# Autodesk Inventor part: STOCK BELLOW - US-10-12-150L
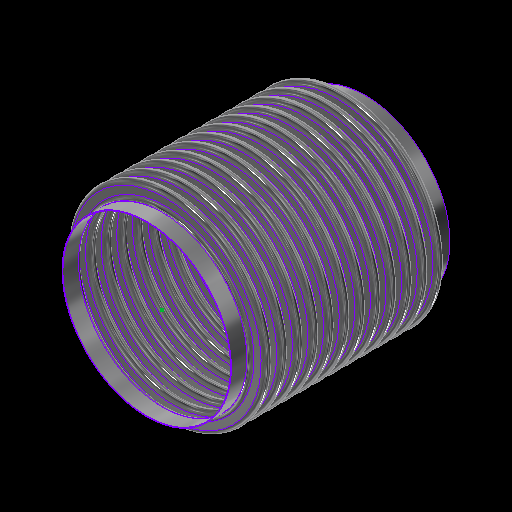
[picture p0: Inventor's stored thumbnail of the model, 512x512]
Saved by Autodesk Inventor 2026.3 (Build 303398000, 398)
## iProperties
Category: 18 GA (0.048 THICK)
RuleStatus: InUse
Created: 2024-01
Part Number: STOCK BELLOW - US-10-12-150L
Project: =STOCK BELLOWS: <Stock Number><SFILL>
Material: ASTM A240-304
Description: =STOCK BELLOWS: <Stock Number>, <SID_> I.D., <SOD_> O.D., <SPLY_> PLY, <Category>, <SNET_CONS> CONS.<PITCH_><STANGENT_> TANGENT<SFILL>
Document SubType Name: Sheet Metal
Designer: GS
Stock Number: U.S-10-12-150L
Surface Area: 15083.6 cm^2
Volume: 915.651 cm^3
Sheet Metal Rule: Default
Appearance: STAINLESS STEEL
Mass: 7377.66 g
Density: 8.05729 g/cm^3
THK: 0.036
ID: 3.500
OD: 4.250
CONS_: 2
PITCH: 0.500
TANGENT: 0.500
BELLOWS_UPSET: 0.000
d79: 1.000
d82: 1.000
d83: 26.000
d84: 24.000
d174: 8
d214: 8
STHK_: 0.048
SID_: 10.750
SOD_: 12.750
SPITCH_: 1.000
STANGENT__: 1.000
SBELLOWS_UPSET_: 0.000
SDIFF_TAN: 1.000
d252: 2
d275: 2
d287: 0.050
d289: 0.500
d290: 0.000
SOD_NECK: 10 7/8
PLY: 1
PSET: 4.178
PBAR: 1.035
COUNTER: 1.500
NET_TUBE: 3.071
CONS: 2
S_CONS: 0
NET_CONS: 2
ID_M: 88.90 mm
OD_M: 107.95 mm
THK_M: 0.91 mm
ID_U: 3.500 in
OD_U: 4.250 in
THK_U: 0.036 in
TANGENT2: 0.500
TAN_TO_TAN: 1.000 in
d80: 2.571
d81: 10
SID: 2.375
SCONS_: 12
SPITCH: 0.250
STANGENT_: 1.000
SBELLOWS_UPSET: 0.000
SNET_CONS: 12
SS_CONS: 0
SCONS: 8
d190: 8
d191: 1
d192: 1
d193: 8
d194: 0
SIZE: 10.00
PRESSURE: 150
d230: 8
STANGENT: 4.000
SPLY_: 1
d233: 8
d234: 0
d263: 2
d265: 1
d268: 2
d269: 0
d286: 2
d288: 1
d291: 2
d292: 0
SREROLL: 0.750
BLETP: 1.000 ul
PRES_Copy: 85
MATTABLE: 20 GA (0.036 THICK)
PART_NUMBER: U.S-10-12-150L
PITCH_: =, <SPITCH_> PITCH,
CFILL: .
SFILL: .
MESH: ,
COMP: 2.22
EXT: 1.11
LAT: 0.75
ANG: 573
ASR: 1990
LSR: 2575
ANSR: 539
PRES: 150
COMPM: 22.2
EXTM: 11.1
LATM: 7.50
ASRM: 348.509
PRESM: 10.342
LSRM: 450.960
ANSRM: 94.395
TEMPMIN: 20
TEMPMAX: 800
TEMPMINM: -7
TEMPMAXM: 427
WEIGHTM: 7.378
WEIGHT: 16.265
Author: GS
Keywords: 20 GA (0.036 THICK)
Comments: =STOCK BELLOW - <STOCK NUMBER>
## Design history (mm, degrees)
sketch "Sketch2"
  geometry: L1 (0, -177.245)-(0, 562.856) reference; L2 (45.364, 0)-(44.45, 0); L3 (48.082, -2.718)-(50.343, -2.718); L4 (48.082, -3.632)-(50.343, -3.632); L5 (50.343, -9.982)-(48.082, -9.982); L6 (50.343, -9.068)-(48.082, -9.068); L7 (45.364, -12.7)-(44.45, -12.7); L8 (48.082, 0)-(48.082, -12.7); L9 (50.343, -6.35)-(53.975, -6.35); L10 (44.45, 0)-(44.45, -12.7); L11 (20.376, 102.841)-(20.376, 101.926); L12 (58.262, 457.127)-(58.262, 349.177); L13 (58.262, 444.427)-(58.262, 336.477); L14 (93.133, -58.817)-(93.133, -71.517); L15 (118.746, -66.401)-(118.746, -66.401); L16 (50.343, -9.068)-(50.343, -9.982); L17 (48.082, -9.068)-(48.082, -9.982); L18 (48.082, -9.525)-(50.343, -9.525); L19 (53.975, 0)-(53.975, -12.7); L20 (-50.343, -9.068)-(-50.343, -9.982); L21 (-50.343, -2.718)-(-48.082, -2.718); L22 (-50.343, -3.632)-(-48.082, -3.632); L23 (-48.082, -9.068)-(-50.343, -9.068); L24 (-50.343, -9.525)-(-48.082, -9.525); L25 (-48.082, -9.982)-(-50.343, -9.982); L26 (-48.082, -9.068)-(-48.082, -9.982); L27 (-44.45, 0.653)-(-44.45, -12.047); L28 (-48.082, -6.35)-(-44.45, -6.35); L29 (-50.343, 0.653)-(-50.343, -12.7); L30 (-53.061, 0)-(-53.975, 0); L31 (-53.975, 0)-(-53.975, -12.7); L32 (-53.061, -12.7)-(-53.975, -12.7); A1 r 2.718 centre (48.082, 0) between (45.364, 0) and (48.082, -2.718); A2 r 3.632 centre (48.082, 0) between (44.45, 0) and (48.082, -3.632); A3 r 3.632 centre (50.343, -6.35) between (50.343, -9.982) and (50.343, -2.718); A4 r 2.718 centre (50.343, -6.35) between (50.343, -9.068) and (50.343, -3.632); A5 r 2.718 centre (48.082, -12.7) between (48.082, -9.982) and (45.364, -12.7); A6 r 3.632 centre (48.082, -12.7) between (48.082, -9.068) and (44.45, -12.7); A7 r 3.175 centre (50.343, -6.35) between (50.343, -9.525) and (53.518, -6.35); A8 r 3.175 centre (48.082, -12.7) between (48.082, -9.525) and (44.907, -12.7); A9 r 2.718 centre (-50.343, -12.7) between (-50.343, -9.982) and (-53.061, -12.7); A10 r 2.718 centre (-48.082, -6.35) between (-48.082, -9.068) and (-48.082, -3.632); A11 r 3.175 centre (-48.082, -6.35) between (-48.082, -9.525) and (-44.907, -6.35); A12 r 3.632 centre (-48.082, -6.35) between (-48.082, -9.982) and (-48.082, -2.718); A13 r 3.175 centre (-50.343, -12.7) between (-50.343, -9.525) and (-53.518, -12.7); A14 r 3.632 centre (-50.343, -12.7) between (-50.343, -9.068) and (-53.975, -12.7); A15 r 2.718 centre (-50.343, 0) between (-53.061, 0) and (-50.343, -2.718); A16 r 3.632 centre (-50.343, 0) between (-53.975, 0) and (-50.343, -3.632); 10 further points
  constraints: 62 end point, 38 point on circle, 20 tangent, 16 centre point, 12 parallel, 9 midpoint, 7 vertical, 6 coincident, 6 concentric, 6 point on line, 4 equal radius, 4 perpendicular, 3 horizontal, 1 collinear, 1 horizontal alignment, 10 other
  dimensions: "THK" = 0.9144 distance of L11.start L11.end; "ID" = 88.9 distance of L11.end point (20.376, 13.026); "OD" = 107.95 distance of L12.start L12.end; "PITCH" = 12.7 distance of L12.start L13.start; "TANGENT" = 12.7 distance of L14.start L14.end; "BELLOWS_UPSET" = 0 distance of L15.start L15.end; "d43" = 88.9 diameter of L10 L1 (= ID); "d44" = 107.95 diameter of L9.end L1 (= OD); "d45" = 0.9144 distance between parallel lines of L5 L6 (computed from THK, PLY); "d46" = 3.6322 radius of A3 (computed from PITCH, THK, PLY); "UPSET_PITCH" = 12.7 distance of L2.end L7.end (derived); "SIDEWALL_ANGLE" = 360 deg dimension on L3 L9 (derived); "CON_GAP" = 5.4356 distance of point (48.082, -9.068) point (48.082, -3.632) (derived); "TAN1" = 4.98728 dimension on A8 (derived); "TAN2" = 4.98728 dimension on A7 (derived); "LEG1" = 2.2606 distance of L18.start L18.end (derived); "d278" = 0.9144 distance between parallel lines of L25 L23 (derived); "d279" = 3.6322 radius of A12 (derived); "d280" = 12.7 distance of L30.end L31.end (derived); "d281" = 360 deg dimension on L21 L28 (derived); "d282" = 5.4356 distance of point (-50.343, -9.068) point (-50.343, -3.632) (derived); "d283" = 4.98728 dimension on A13 (derived); "d284" = 4.98728 dimension on A11 (derived); "d285" = 2.2606 distance of L24.start L24.end (derived); "d293" = 88.9 diameter of L27 L1 (derived); "d294" = 107.95 diameter of L31 L1 (derived)
  node "Sketch Rectangular Pattern1" dims "d31" = 25.4, "ID" = 88.9
  node "Sketch Rectangular Pattern2" dims "d39" = 25.4, "PITCH" = 12.7
revolve "CONS" stored, may be unused: angle "d48" = 90 deg
node "BELLOW MIDPLANE"
pattern_linear "Rectangular Pattern2" dims "d52" = 12.7 (= UPSET_PITCH)
sketch "Sketch5"
  geometry: C1 r 45.364 at (0, 0) reference; C2 r 44.45 at (0, 0) reference
extrude "TANGENT" new body sketch "Sketch5" distance "d53" = 12.7 (= TANGENT); taper "d54" = 0 deg
revolve "SAMETAN" stored, may be unused: angle "d65" = 90 deg
revolve "DIFFTAN" stored, may be unused: angle "d70" = 90 deg
sketch "Sketch9"
  geometry: L1 (53.319, 0)-(-53.319, 0) reference; L2 (0, -17.78)-(0, 17.78) reference; L3 (38.085, 0)-(-38.085, 0); L4 (38.085, -11.906)-(38.085, 11.906); L5 (25.385, -11.906)-(25.385, 11.906); L6 (13.15, 11.906)-(13.15, -11.906); L7 (-25.385, -11.906)-(-25.385, 11.906); L8 (-38.085, -11.906)-(-38.085, 11.906); L9 (37.291, -11.906)-(37.291, 11.906); L10 (38.085, -11.906)-(37.291, -11.906); L11 (38.085, 11.906)-(37.291, 11.906); L12 (13.546, 11.906)-(12.753, 11.906); L13 (12.753, 11.906)-(12.753, -11.906); L14 (12.753, -11.906)-(13.546, -11.906); L15 (13.546, -11.906)-(13.546, 11.906); L16 (-13.546, 11.906)-(-13.546, -11.906); L17 (-13.15, 11.906)-(-13.15, -11.906); L18 (-13.546, -11.906)-(-12.753, -11.906); L19 (-12.753, -11.906)-(-12.753, 11.906); L20 (-12.753, 11.906)-(-13.546, 11.906); L21 (-38.085, -11.906)-(-37.291, -11.906); L22 (-37.291, -11.906)-(-37.291, 11.906); L23 (-37.291, 11.906)-(-38.085, 11.906); L24 (-38.085, 11.906)-(-38.085, -11.906); L25 (38.085, -0.397)-(-38.085, -0.397); L26 (-38.085, -0.397)-(-38.085, 0.397); L27 (-38.085, 0.397)-(38.085, 0.397); L28 (38.085, 0.397)-(38.085, -0.397); L29 (-38.085, 11.906)-(38.085, 11.906); L30 (38.085, 11.906)-(38.085, 12.7); L31 (38.085, 12.7)-(-38.085, 12.7); L32 (-38.085, 12.7)-(-38.085, 11.906); L33 (38.085, -11.906)-(-38.085, -11.906); L34 (-38.085, -11.906)-(-38.085, -12.7); L35 (-38.085, -12.7)-(38.085, -12.7); L36 (38.085, -12.7)-(38.085, -11.906); 30 further points
  constraints: 68 end point, 13 midpoint, 13 parallel, 8 horizontal, 7 perpendicular, 6 equal length, 3 point on line, 2 vertical, 14 other
  dimensions: "d115" = 23.8125 distance of L4.start L4.end (derived); "d116" = 12.7 distance between parallel lines of L4 L5 (derived); "d117" = 12.23516 distance between parallel lines of L5 L6 (derived); "d125" = 38.53427 distance between parallel lines of L7 L6 (derived); "d127" = 12.7 distance between parallel lines of L8 L7 (derived); "d128" = 24.93516 distance between parallel lines of L6 L4 (derived); "d130" = 76.16943 distance between parallel lines of L8 L4 (derived); "RULER_THK" = 0.79375 distance between parallel lines of L4 L9; "d135" = 0.79375 distance of L13.end L14.end (derived); "d138" = 26.29911 distance of L13.end L16.end (derived); "d143" = 0.79375 distance of L22.end L8.end (derived); "d144" = 0.79375 distance between parallel lines of L27 L25 (derived)
extrude "RULER" join sketch "Sketch9" distance "d149" = 0.79375 (derived); taper "d150" = 0 deg
extrude "BARS" join sketch "Sketch9" distance "d151" = 0.79375 (derived); taper "d152" = 0 deg
pattern_linear "Rectangular Pattern4" dims "d155" = 26.29911 (derived)
sketch "Sketch13"
  geometry: L1 (93.149, -52.467)-(93.149, -77.867); L2 (137.744, 0)-(136.525, 0); L3 (137.744, -25.4)-(136.525, -25.4); L4 (154.965, -19.66)-(143.485, -19.66); L5 (154.965, -18.44)-(143.485, -18.44); L6 (154.965, -12.7)-(161.925, -12.7); L7 (143.485, -5.74)-(154.965, -5.74); L8 (143.485, 0)-(143.485, -25.4); L9 (136.525, 0)-(136.525, -25.4); L10 (58.254, -172.581)-(58.254, -496.431); L11 (58.254, -197.981)-(58.254, -521.831); L12 (58.254, -248.781)-(58.254, -572.631); L13 (58.254, -274.181)-(58.254, -598.031); L14 (58.254, -299.581)-(58.254, -623.431); L15 (58.254, -324.981)-(58.254, -648.831); L16 (58.254, -350.381)-(58.254, -674.231); L17 (58.254, -223.381)-(58.254, -547.231); L18 (20.376, 103.145)-(20.376, 101.926); L19 (143.485, -6.96)-(154.965, -6.96); L20 (0, -829.706)-(0, 258.621) reference; L21 (-32.385, 0)-(194.31, 0) reference; A1 r 5.74 centre (143.485, 0) between (137.744, 0) and (143.485, -5.74); A2 r 5.74 centre (143.485, -25.4) between (143.485, -19.66) and (137.744, -25.4); A3 r 6.96 centre (143.485, -25.4) between (143.485, -18.44) and (136.525, -25.4); A4 r 5.74 centre (154.965, -12.7) between (154.965, -18.44) and (154.965, -6.96); A5 r 6.96 centre (154.965, -12.7) between (154.965, -19.66) and (154.965, -5.74); A6 r 6.96 centre (143.485, 0) between (136.525, 0) and (143.485, -6.96); 6 further points; 1 other entity
  constraints: 38 end point, 15 point on circle, 9 tangent, 6 centre point, 6 parallel, 5 vertical alignment, 4 point on line, 4 vertical, 3 coincident, 3 concentric, 2 collinear, 2 equal radius, 1 horizontal, 1 perpendicular, 23 other
  dimensions: "SBELLOWS_UPSET_" = 0 distance of point (118.762, -66.401) point (118.762, -66.401); "STOTAL_THK_BELLOW__" = 1.2192 distance between parallel lines of L4 L5 (derived); "d224" = 6.9596 radius of A5 (derived); "d225" = 25.4 distance of L2.end L3.end (derived); "SSIDEWALL_ANGLE_" = 360 deg dimension on L7 L6 (derived); "SSCON_GAP_" = 11.4808 distance of point (143.485, -18.44) point (143.485, -6.96) (derived); "d235" = 273.05 diameter of L9 L20 (derived); "d236" = 323.85 diameter of L6.end L20 (derived)
  node "Sketch Rectangular Pattern4" dims "d228" = 25.4
  node "Sketch Rectangular Pattern5" dims "d229" = 25.4
revolve "SBELLOW" stored, may be unused: angle "d197" = 90 deg
pattern_linear "Rectangular Pattern5" dims "d204" = 25.4 (derived)
revolve "STANGENT" stored, may be unused: angle "d240" = 90 deg
revolve "SSAMETAN" stored, may be unused: angle "d241" = 90 deg
revolve "SDIFFTAN" stored, may be unused: angle "d246" = 90 deg
revolve "INVCON" stored, may be unused: angle "d295" = 90 deg
pattern_linear "Rectangular Pattern6" dims "d298" = 12.7 (derived)
revolve "INVTANGENT" stored, may be unused: angle "d302" = 90 deg
revolve "INVSAMETAN" stored, may be unused: angle "d307" = 90 deg
revolve "INVDIFFTAN" stored, may be unused: angle "d312" = 90 deg
sketch "ID BELLOW MOUNT CALC"
  geometry: L1 (44.45, 0)-(38.1, 0); L2 (38.1, 0)-(38.1, 12.7); L3 (38.1, 12.7)-(44.45, 12.7); L4 (44.45, 12.7)-(44.45, 0); L5 (36.513, 12.7)-(35.598, 12.7); L6 (35.598, 12.7)-(35.598, 0); L7 (35.598, 0)-(36.513, 0); L8 (36.513, 0)-(36.513, 12.7); L9 (0, -2.54)-(0, 15.24) reference; L10 (-8.89, 0)-(53.34, 0) reference; 1 further point
  constraints: 16 end point, 5 parallel, 2 collinear, 2 horizontal, 2 perpendicular
  dimensions: "d314" = 12.7 distance of L5.end L6.end (derived); "d315" = 0.9144 distance of L5.start L5.end (derived); "IG" = 1.5875 distance between parallel lines of L2 L8; "PIPE_OD" = 88.9 diameter of L4 L9; "PIPE_WALL" = 6.35 distance of L2.end L3.end; "ID_MT_BELLOW" = 71.1962 diameter of L6 L9 (derived)
revolve "CFILL" stored, may be unused: angle "d320" = 90 deg
pattern_linear "Rectangular Pattern7" dims "d323" = 12.7 (derived)
revolve "SFILL" stored, may be unused: angle "d324" = 90 deg
pattern_linear "Rectangular Pattern8" dims "d327" = 25.4 (derived)
node "STOCK BELLOW MIDPLANE"
node "BELLOW"
sketch "Sketch6"
  geometry: L1 (-12.7, 45.364)-(0, 45.364); L2 (0, 45.364)-(0, 44.45); L3 (0, 44.45)-(-12.7, 44.45); L4 (-12.7, 44.45)-(-12.7, 45.364); L5 (10.16, 0)-(-60.96, 0) reference; L6 (-38.1, -89.422)-(-38.1, 153.44) reference; 1 further point
  constraints: 8 end point, 2 parallel, 1 horizontal, 1 perpendicular
  dimensions: "d61" = 12.7 distance of L2.end L3.end (derived); "d62" = 0.9144 distance of L1.end L2.end (derived); "d63" = 88.9 diameter of L3 L5 (derived); "d64" = 25.4 distance between parallel lines of L4 L6 (derived)
sketch "Sketch12"
  geometry: 1 further point
sketch "Sketch14"
  geometry: L1 (-25.4, 137.744)-(0, 137.744); L2 (0, 137.744)-(0, 136.525); L3 (0, 136.525)-(-25.4, 136.525); L4 (-25.4, 136.525)-(-25.4, 137.744); L5 (5.08, 0)-(-30.48, 0) reference; L6 (0, -27.549)-(0, 165.293) reference; 1 further point
  constraints: 8 end point, 2 parallel, 1 collinear, 1 horizontal, 1 perpendicular
  dimensions: "d237" = 1.2192 distance of L3.end L1.start (derived); "d238" = 273.05 diameter of L3 L5 (derived); "d239" = 25.4 distance of L1.start L1.end (derived); "SOD_NECK" = 275.4884 diameter of L1 L5 (derived)
sketch "Sketch15"
  geometry: L1 (-27.549, 0)-(165.293, 0) reference; L2 (136.525, -304.8)-(137.744, -304.8); L3 (137.744, -304.8)-(137.744, -330.2); L4 (137.744, -330.2)-(136.525, -330.2); L5 (136.525, -330.2)-(136.525, -304.8); L6 (0, -398.78)-(0, 81.28) reference; 1 further point
  constraints: 8 end point, 2 parallel, 1 horizontal, 1 perpendicular
  dimensions: "d205" = 25.4 distance of L4.end L2.start (derived); "d206" = 1.2192 distance of L3.end L4.end (derived); "d207" = 273.05 diameter of L5 L6 (derived); "d208" = 304.8 distance between parallel lines of L1 L2 (derived)
node "TANGENT_"
node "SAME_TAN"
sketch "Sketch8"
  geometry: L1 (45.364, -25.4)-(44.45, -25.4); L2 (44.45, -25.4)-(44.45, -38.1); L3 (44.45, -38.1)-(45.364, -38.1); L4 (45.364, -38.1)-(45.364, -25.4); L5 (0, -48.26)-(0, 22.86) reference; L6 (-89.422, 0)-(153.44, 0) reference; 1 further point
  constraints: 8 end point, 2 parallel, 1 horizontal, 1 perpendicular
  dimensions: "d66" = 88.9 diameter of L2 L5 (derived); "TOTAL_THK_BELLOW" = 0.9144 distance of L2.end L3.end (derived); "d68" = 25.4 distance between parallel lines of L1 L6 (derived); "d69" = 12.7 distance of L1.end L2.end (derived)
node "DIFF_TAN"
node "Sketch Rectangular Pattern3" dims "d138" = 26.29911 (derived), "d141" = 25.4
node "SBELLOW_"
node "STANGENT_"
node "SSAME_TAN"
sketch "Sketch16"
  geometry: L1 (137.744, -304.8)-(136.525, -304.8); L2 (136.525, -304.8)-(136.525, -330.2); L3 (136.525, -330.2)-(137.744, -330.2); L4 (137.744, -330.2)-(137.744, -304.8); L5 (0, -398.78)-(0, 81.28) reference; L6 (-27.549, 0)-(165.293, 0) reference; 1 further point
  constraints: 8 end point, 2 parallel, 1 horizontal, 1 perpendicular
  dimensions: "SDIFF_TAN" = 25.4 distance of L3.end L1.start; "d243" = 1.2192 distance of L2.end L3.end (derived); "d244" = 304.8 distance between parallel lines of L1 L6 (derived); "d245" = 273.05 diameter of L2 L5 (derived)
node "SDIFF_TAN"
body "Solid15"
sketch "Sketch17"
  geometry: L1 (53.975, 12.7)-(53.061, 12.7); L2 (53.061, 12.7)-(53.061, 0); L3 (53.061, 0)-(53.975, 0); L4 (53.975, 0)-(53.975, 12.7); L5 (0, -2.54)-(0, 15.24) reference; L6 (-10.795, 0)-(64.77, 0) reference; 2 further points
  constraints: 8 end point, 2 parallel, 1 horizontal, 1 midpoint, 1 perpendicular, 1 point on line
  dimensions: "INVTANGENT" = 12.7 distance of L3.end L1.start (derived); "d300" = 0.9144 distance of L1.start L1.end (derived); "d301" = 107.95 diameter of L4 L5 (derived)
body "Solid16"
sketch "Sketch18"
  geometry: L1 (53.975, -25.4)-(53.061, -25.4); L2 (53.061, -25.4)-(53.061, -38.1); L3 (53.061, -38.1)-(53.975, -38.1); L4 (53.975, -38.1)-(53.975, -25.4); L5 (-10.795, 0)-(64.77, 0) reference; L6 (0, -48.26)-(0, 22.86) reference; 1 further point
  constraints: 8 end point, 2 parallel, 1 horizontal, 1 perpendicular
  dimensions: "d303" = 25.4 distance between parallel lines of L1 L5 (derived); "d304" = 12.7 distance of L3.end L1.start (derived); "d305" = 0.9144 distance of L2.end L3.end (derived); "d306" = 107.95 diameter of L4 L6 (derived)
body "Solid17"
sketch "Sketch19"
  geometry: L1 (53.975, -25.4)-(53.061, -25.4); L2 (53.061, -25.4)-(53.061, -38.1); L3 (53.061, -38.1)-(53.975, -38.1); L4 (53.975, -38.1)-(53.975, -25.4); L5 (0, -48.26)-(0, 22.86) reference; L6 (-10.795, 0)-(64.77, 0) reference; 1 further point
  constraints: 8 end point, 2 parallel, 1 horizontal, 1 perpendicular
  dimensions: "d308" = 12.7 distance of L1.end L2.end (derived); "d309" = 107.95 diameter of L4 L5 (derived); "d310" = 0.9144 distance of L2.end L3.end (derived); "d311" = 25.4 distance between parallel lines of L1 L6 (derived)
body "Solid18"
body "Solid19"
body "Solid20"
other parameters: "BMPL" = -152.4, "PSET" = 106.1212 (computed from OD, THK, PLY) [user parameter], "PBAR" = 26.29911 (= 0.570796 x PITCH + OD - ID) [user parameter; used in 1 equation term], "COUNTER" = 15 [user parameter], "NET_TUBE" = 77.99823 (computed from CONS_, PBAR, TANGENT) [user parameter], "S_CONS" = 0 [user parameter; used in 1 equation term], "ID_M" = 88.9 (= ID) [user parameter], "OD_M" = 107.95 (= OD) [user parameter], "THK_M" = 0.9144 (= THK) [user parameter], "ID_U" = 88.9 (= ID) [user parameter], "OD_U" = 107.95 (= OD) [user parameter], "THK_U" = 0.9144 (= THK) [user parameter], "D_UNITS" = 0 [user parameter], "TANGENT2" = 12.7 [user parameter], "TAN_TO_TAN" = 25.4 [user parameter], "OD_NECK" = 90.7288 [user parameter], "d79" = 25.4, "d80" = 65.29823 [user parameter], "d82" = 25.4, "d83" = 660.4, "d84" = 609.6, "sa_0" = 4, "FRAME_THK" = 0.79375 [user parameter], "CON_FLAT" = 12.23516 [user parameter], "SID" = 60.325 [user parameter], "SPITCH" = 6.35 [user parameter], "STANGENT_" = 25.4 [user parameter], "SBELLOWS_UPSET" = 0 [user parameter], "SS_CONS" = 0 [user parameter], "STAN_TO_TAN_" = 304.8 [user parameter], "d100" = 1.2192 [user parameter], "d191" = 25.4 [user parameter], "d194" = 0 [user parameter], "STANGENT" = 101.6 [user parameter], "d234" = 0 [user parameter], "SUPSET_PITCH_" = 25.4 [user parameter], "d269" = 0 [user parameter], "d287" = 1.27, "d289" = 12.7, "d290" = 0, "d292" = 0 [user parameter], "Thickness" = 3.048 (derived), "KFactor" = 4.4, "BendRadius" = 3.048 (derived), "BendReliefWidth" = 3.048 (derived), "BendReliefDepth" = 1.524 (derived), "CornerReliefSize" = 12.192 (derived), "SeamGap" = 0.00508, "MinimumRemnant" = 6.096 (derived), "TransitionRadius" = 3.048 (derived), "JacobiRadiusSize" = 3.048 (derived), "GapSize" = 3.048 (derived), "SREROLL" = 19.05 [user parameter], "CUR_STK_PITCH" = 25.4 [user parameter], "d328" = -152.4 (derived), "ASR" = 19900 [user parameter], "LSR" = 25750 [user parameter], "BLETP" = 1 [user parameter], "ASRM" = 3485.087 [user parameter], "PRESM" = 103.41975 [user parameter], "LSRM" = 4509.5975 [user parameter], "ANSRM" = 943.9507 [user parameter], "TEMPMIN" = 2664.83333 [user parameter], "TEMPMAX" = 6998.16667 [user parameter], "TEMPMINM" = 2664.83333 [user parameter], "TEMPMAXM" = 6998.16667 [user parameter], "WEIGHT" = 73.77664 [user parameter], "WEIGHTM" = 0.07378 [user parameter]
